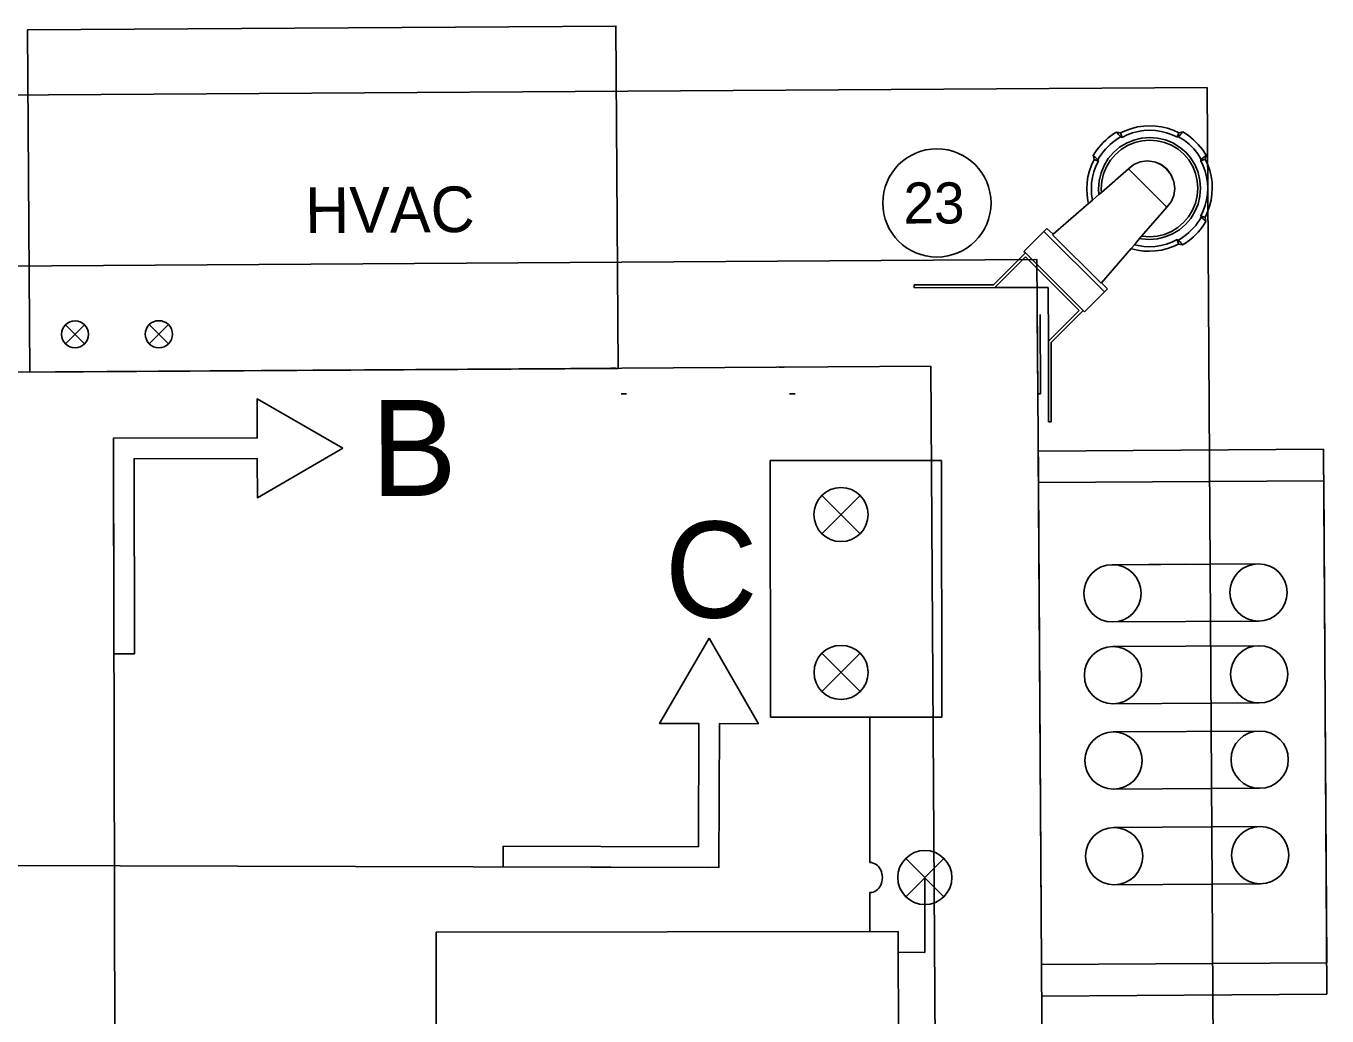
# Model space of a CAD drawing. Extents: x -2.6 to 16.3, y -2.7 to 7.5.
# Drawn here: x 12.505 to 16.306, y 4.389 to 7.281 of the extents above; entities that cross this region are included whole.
import ezdxf

# ---------------------------------------------------------------- set-up
doc = ezdxf.new("R2010")
doc.units = 0
for name, color, linetype in [('Default', 7, 'Continuous'), ('HS_Concrete_Object', 7, 'Continuous'), ('HS_Dimensions_and_Text', 7, 'Continuous'), ('HS_Electrical_Conduit', 7, 'Continuous'), ('HS_Electrical_Devices', 7, 'Continuous'), ('HS_Electrical_Enclosure', 7, 'Continuous'), ('HS_Existing', 7, 'Continuous'), ('PM_Pr_White', 7, 'Continuous'), ('SH_Matchline', 7, 'Continuous')]:
    doc.layers.add(name, color=color, linetype=linetype)

msp = doc.modelspace()

# ---------------------------------------------------------------- linework, layer by layer
at = {"layer": 'Default'}
for p, q in [((15.4598, 6.4421), (15.4613, 6.2066)), ((15.468, 6.4387), (15.4695, 6.2067)), ((15.4695, 6.2067), (15.4613, 6.2066))]:
    msp.add_line(p, q, dxfattribs=at)
at = {"layer": 'HS_Concrete_Object'}
for points in [[(14.235, 6.281), (14.2286, 7.281), (12.5099, 7.27), (12.5163, 6.27)], [(15.9556, 7.1018), (-0.0446, 6.9998), (0, 0), (16.0002, 0.1019)]]:
    msp.add_lwpolyline(points, close=True, dxfattribs=at)
for points in [[(15.4629, 5.9473), (15.4588, 6.5986), (0.4591, 6.5025), (0.4974, 0.5032), (0.9916, 0.5063)], [(0.7399, 0.7823), (0.7054, 6.1941), (15.1483, 6.2872)], [(15.1804, 1.2511), (15.1483, 6.2872)], [(15.4928, 1.2531), (15.462, 6.1014)]]:
    msp.add_lwpolyline(points, dxfattribs=at)
at = {"layer": 'HS_Dimensions_and_Text'}
for points in [[(13.4309, 6.0481), (13.1806, 6.1919), (13.1809, 6.0776), (12.7609, 6.0767), (12.7622, 5.4467), (12.8222, 5.4468), (12.821, 6.0168), (13.181, 6.0176), (13.1812, 5.9032)], [(14.5016, 5.4933), (14.6452, 5.2429), (14.5309, 5.2432), (14.5297, 4.8232), (13.8997, 4.825), (13.8998, 4.885), (14.4698, 4.8834), (14.4709, 5.2434), (14.3565, 5.2437)]]:
    msp.add_lwpolyline(points, close=True, dxfattribs=at)
for points in [[(12.7609, 6.0463), (12.7712, 1.2501)], [(5.2174, 4.8497), (14.4996, 4.8233)]]:
    msp.add_lwpolyline(points, dxfattribs=at)
at = {"layer": 'HS_Electrical_Conduit'}
for p, q in [((15.6787, 5.7075), (16.1056, 5.7102)), ((15.6798, 5.5402), (16.1067, 5.543)), ((15.6803, 5.4682), (16.1071, 5.4709)), ((15.6813, 5.301), (16.1082, 5.3037)), ((15.6818, 5.2189), (16.1087, 5.2217)), ((15.6829, 5.0517), (16.1098, 5.0544)), ((15.6836, 4.9398), (16.1105, 4.9425)), ((15.1312, 4.7937), (15.1314, 4.575)), ((15.6847, 4.7725), (16.1116, 4.7753)), ((15.1314, 4.575), (15.0536, 4.5752))]:
    msp.add_line(p, q, dxfattribs=at)
for centre in [(15.6793, 5.6239), (16.1061, 5.6266), (15.6808, 5.3846), (16.1077, 5.3873), (15.6824, 5.1353), (16.1093, 5.138), (16.111, 4.8589), (15.6841, 4.8562)]:
    msp.add_circle(centre, 0.0836, dxfattribs=at)
at = {"layer": 'HS_Electrical_Devices'}
for p, q in [((15.6748, 6.9602), (15.6671, 6.9542)), ((15.6828, 6.9658), (15.6748, 6.9602)), ((15.6911, 6.971), (15.6828, 6.9658)), ((15.6911, 6.971), (15.6936, 6.9682)), ((15.6911, 6.971), (15.7029, 6.9685)), ((15.6936, 6.9682), (15.6961, 6.9654)), ((15.7033, 6.957), (15.6951, 6.9521)), ((15.6961, 6.9654), (15.6985, 6.9626)), ((15.6985, 6.9626), (15.7009, 6.9598)), ((15.7009, 6.9598), (15.7033, 6.957)), ((15.719, 6.9759), (15.7029, 6.9685)), ((15.7072, 6.9557), (15.7029, 6.9685)), ((15.7072, 6.9557), (15.7033, 6.957)), ((15.7224, 6.963), (15.7072, 6.9557)), ((15.7357, 6.9818), (15.719, 6.9759)), ((15.7382, 6.9687), (15.7224, 6.963)), ((15.7528, 6.9861), (15.7357, 6.9818)), ((15.7545, 6.9729), (15.7382, 6.9687)), ((15.7703, 6.9887), (15.7528, 6.9861)), ((15.7711, 6.9754), (15.7545, 6.9729)), ((15.7879, 6.9555), (15.7645, 6.9536)), ((15.7879, 6.9896), (15.7703, 6.9887)), ((15.7879, 6.9763), (15.7711, 6.9754)), ((15.8056, 6.9889), (15.7879, 6.9896)), ((15.8047, 6.9756), (15.7879, 6.9763)), ((15.8112, 6.9537), (15.7879, 6.9555)), ((15.8213, 6.9731), (15.8047, 6.9756)), ((15.823, 6.9864), (15.8056, 6.9889)), ((15.8376, 6.9691), (15.8213, 6.9731)), ((15.8402, 6.9822), (15.823, 6.9864)), ((15.8534, 6.9634), (15.8376, 6.9691)), ((15.8569, 6.9764), (15.8402, 6.9822)), ((15.8534, 6.9634), (15.8693, 6.9565)), ((15.8729, 6.9691), (15.8569, 6.9764)), ((15.8693, 6.9565), (15.8696, 6.9595)), ((15.8724, 6.9576), (15.8693, 6.9565)), ((15.8729, 6.9691), (15.8696, 6.9595)), ((15.8724, 6.9576), (15.8748, 6.9604)), ((15.8885, 6.9475), (15.8724, 6.9576)), ((15.8729, 6.9691), (15.8847, 6.9717)), ((15.8748, 6.9604), (15.8773, 6.9633)), ((15.8773, 6.9633), (15.8797, 6.9661)), ((15.8797, 6.9661), (15.8822, 6.9689)), ((15.8822, 6.9689), (15.8847, 6.9717)), ((15.901, 6.9611), (15.8847, 6.9717)), ((15.9161, 6.9488), (15.901, 6.9611)), ((15.6335, 6.9189), (15.6279, 6.9109)), ((15.6395, 6.9266), (15.6335, 6.9189)), ((15.6459, 6.934), (15.6395, 6.9266)), ((15.6526, 6.9411), (15.6459, 6.934)), ((15.6597, 6.9479), (15.6526, 6.9411)), ((15.659, 6.9213), (15.6528, 6.914)), ((15.6655, 6.9282), (15.659, 6.9213)), ((15.6671, 6.9542), (15.6597, 6.9479)), ((15.6724, 6.9348), (15.6655, 6.9282)), ((15.6797, 6.941), (15.6724, 6.9348)), ((15.6873, 6.9467), (15.6797, 6.941)), ((15.7002, 6.9267), (15.6823, 6.9114)), ((15.6951, 6.9521), (15.6873, 6.9467)), ((15.7048, 6.9204), (15.6879, 6.9059)), ((15.7201, 6.939), (15.7002, 6.9267)), ((15.7237, 6.932), (15.7048, 6.9204)), ((15.7418, 6.948), (15.7201, 6.939)), ((15.7442, 6.9406), (15.7237, 6.932)), ((15.7645, 6.9536), (15.7418, 6.948)), ((15.7658, 6.9458), (15.7442, 6.9406)), ((15.7879, 6.9476), (15.7658, 6.9458)), ((15.81, 6.946), (15.7879, 6.9476)), ((15.8315, 6.9409), (15.81, 6.946)), ((15.834, 6.9484), (15.8112, 6.9537)), ((15.852, 6.9325), (15.8315, 6.9409)), ((15.8556, 6.9395), (15.834, 6.9484)), ((15.8709, 6.921), (15.852, 6.9325)), ((15.8755, 6.9273), (15.8556, 6.9395)), ((15.8877, 6.9066), (15.8709, 6.921)), ((15.8933, 6.9122), (15.8755, 6.9273)), ((15.9033, 6.9356), (15.8885, 6.9475)), ((15.9167, 6.9222), (15.9033, 6.9356)), ((15.9298, 6.9351), (15.9161, 6.9488)), ((15.9285, 6.9075), (15.9167, 6.9222)), ((15.9421, 6.92), (15.9298, 6.9351)), ((15.9528, 6.9038), (15.9421, 6.92)), ((15.6254, 6.8907), (15.6179, 6.8747)), ((15.6279, 6.9109), (15.6228, 6.9026)), ((15.6256, 6.9001), (15.6228, 6.9026)), ((15.6254, 6.8907), (15.6228, 6.9026)), ((15.6381, 6.8865), (15.6254, 6.8907)), ((15.6284, 6.8976), (15.6256, 6.9001)), ((15.6312, 6.8952), (15.6284, 6.8976)), ((15.6381, 6.8865), (15.6309, 6.8713)), ((15.634, 6.8928), (15.6312, 6.8952)), ((15.6369, 6.8904), (15.634, 6.8928)), ((15.6417, 6.8985), (15.6369, 6.8904)), ((15.6369, 6.8904), (15.6381, 6.8865)), ((15.6471, 6.9064), (15.6417, 6.8985)), ((15.6528, 6.914), (15.6471, 6.9064)), ((15.6671, 6.8936), (15.6548, 6.8736)), ((15.6735, 6.889), (15.6618, 6.87)), ((15.6823, 6.9114), (15.6671, 6.8936)), ((15.6879, 6.9059), (15.6735, 6.889)), ((15.7415, 6.8765), (15.76, 6.8847)), ((15.76, 6.8847), (15.7803, 6.8875)), ((15.7803, 6.8875), (15.801, 6.8846)), ((15.801, 6.8846), (15.8049, 6.883)), ((15.8049, 6.883), (15.8214, 6.8762)), ((15.8049, 6.883), (15.8205, 6.8764)), ((15.9021, 6.8898), (15.8877, 6.9066)), ((15.9084, 6.8945), (15.8933, 6.9122)), ((15.9136, 6.871), (15.9021, 6.8898)), ((15.9206, 6.8745), (15.9084, 6.8945)), ((15.9387, 6.8915), (15.9285, 6.9075)), ((15.9374, 6.8876), (15.9502, 6.8919)), ((15.9376, 6.8883), (15.9374, 6.8876)), ((15.9374, 6.8876), (15.9446, 6.8724)), ((15.9376, 6.8883), (15.9387, 6.8915)), ((15.9415, 6.8939), (15.9387, 6.8915)), ((15.9444, 6.8963), (15.9415, 6.8939)), ((15.9472, 6.8988), (15.9444, 6.8963)), ((15.95, 6.9012), (15.9472, 6.8988)), ((15.9528, 6.9038), (15.95, 6.9012)), ((15.9528, 6.9038), (15.9502, 6.8919)), ((15.9576, 6.8759), (15.9502, 6.8919)), ((15.612, 6.858), (15.6078, 6.8408)), ((15.6179, 6.8747), (15.612, 6.858)), ((15.6252, 6.8555), (15.621, 6.8391)), ((15.6309, 6.8713), (15.6252, 6.8555)), ((15.6459, 6.8519), (15.6403, 6.8291)), ((15.6548, 6.8736), (15.6459, 6.8519)), ((15.6471, 6.795), (15.7263, 6.8635)), ((15.6481, 6.8279), (15.6533, 6.8495)), ((15.6618, 6.87), (15.6533, 6.8495)), ((15.7263, 6.8635), (15.7415, 6.8765)), ((15.8378, 6.7522), (15.7263, 6.8635)), ((15.8205, 6.8764), (15.837, 6.8636)), ((15.8214, 6.8762), (15.8377, 6.8636)), ((15.837, 6.8636), (15.8374, 6.8633)), ((15.8374, 6.8633), (15.8505, 6.8464)), ((15.8377, 6.8636), (15.8503, 6.8473)), ((15.8503, 6.8473), (15.8571, 6.8309)), ((15.8505, 6.8464), (15.8571, 6.8309)), ((15.9221, 6.8505), (15.9136, 6.871)), ((15.9295, 6.853), (15.9206, 6.8745)), ((15.9272, 6.829), (15.9221, 6.8505)), ((15.935, 6.8302), (15.9295, 6.853)), ((15.9446, 6.8724), (15.9502, 6.8566)), ((15.9502, 6.8566), (15.9543, 6.8403)), ((15.9634, 6.8593), (15.9576, 6.8759)), ((15.9676, 6.8421), (15.9634, 6.8593)), ((15.9701, 6.8247), (15.9676, 6.8421)), ((15.6052, 6.8233), (15.6043, 6.8057)), ((15.6043, 6.8057), (15.6051, 6.788)), ((15.6078, 6.8408), (15.6052, 6.8233)), ((15.6066, 6.8344), (15.6052, 6.8233)), ((15.6078, 6.8408), (15.6066, 6.8344)), ((15.6185, 6.8225), (15.6176, 6.8057)), ((15.6176, 6.8057), (15.6184, 6.789)), ((15.6198, 6.8323), (15.6185, 6.8225)), ((15.621, 6.8391), (15.6198, 6.8323)), ((15.6403, 6.8291), (15.6385, 6.8058)), ((15.6385, 6.8058), (15.6398, 6.7887)), ((15.6481, 6.8279), (15.6463, 6.8058)), ((15.6463, 6.8058), (15.6471, 6.795)), ((15.8571, 6.8309), (15.8588, 6.8269)), ((15.8588, 6.8269), (15.8617, 6.8063)), ((15.8617, 6.8063), (15.8589, 6.786)), ((15.9271, 6.7848), (15.9289, 6.8069)), ((15.9289, 6.8069), (15.9272, 6.829)), ((15.9349, 6.7836), (15.9368, 6.8069)), ((15.9368, 6.8069), (15.935, 6.8302)), ((15.9543, 6.8403), (15.9568, 6.8237)), ((15.9576, 6.807), (15.9567, 6.7902)), ((15.9568, 6.8237), (15.9576, 6.807)), ((15.97, 6.7894), (15.9709, 6.807)), ((15.9709, 6.807), (15.9701, 6.8247)), ((15.6051, 6.788), (15.6077, 6.7706)), ((15.6077, 6.7706), (15.6096, 6.7625)), ((15.6096, 6.7625), (15.6209, 6.7724)), ((15.6184, 6.789), (15.6209, 6.7724)), ((15.6209, 6.7724), (15.6398, 6.7887)), ((15.6209, 6.7724), (15.6209, 6.7723)), ((15.6398, 6.7887), (15.6471, 6.795)), ((15.8508, 6.7675), (15.8378, 6.7522)), ((15.8589, 6.786), (15.8508, 6.7675)), ((15.9219, 6.7632), (15.9271, 6.7848)), ((15.9294, 6.7608), (15.9349, 6.7836)), ((15.9542, 6.7736), (15.95, 6.7572)), ((15.9567, 6.7902), (15.9542, 6.7736)), ((15.9632, 6.7547), (15.9674, 6.7719)), ((15.9674, 6.7719), (15.97, 6.7894)), ((15.5056, 6.6725), (15.6096, 6.7625)), ((15.8378, 6.7522), (15.7645, 6.6669)), ((15.9018, 6.7237), (15.9134, 6.7427)), ((15.9081, 6.7191), (15.9204, 6.7391)), ((15.9134, 6.7427), (15.9219, 6.7632)), ((15.9204, 6.7391), (15.9294, 6.7608)), ((15.9443, 6.7414), (15.9371, 6.7262)), ((15.95, 6.7572), (15.9443, 6.7414)), ((15.9499, 6.722), (15.9573, 6.738)), ((15.9573, 6.738), (15.9632, 6.7547)), ((15.488, 6.69), (15.4788, 6.6807)), ((15.5056, 6.6725), (15.488, 6.69)), ((15.8515, 6.6807), (15.8705, 6.6923)), ((15.8705, 6.6923), (15.8873, 6.7068)), ((15.8751, 6.686), (15.8929, 6.7013)), ((15.8873, 6.7068), (15.9018, 6.7237)), ((15.8929, 6.7013), (15.9081, 6.7191)), ((15.9097, 6.6845), (15.9163, 6.6914)), ((15.9163, 6.6914), (15.9224, 6.6987)), ((15.9224, 6.6987), (15.9282, 6.7063)), ((15.9282, 6.7063), (15.9335, 6.7142)), ((15.9335, 6.7142), (15.9384, 6.7223)), ((15.9357, 6.6861), (15.9417, 6.6938)), ((15.9371, 6.7262), (15.9499, 6.722)), ((15.9384, 6.7223), (15.9371, 6.7262)), ((15.9384, 6.7223), (15.9412, 6.7199)), ((15.9412, 6.7199), (15.9441, 6.7175)), ((15.9417, 6.6938), (15.9473, 6.7018)), ((15.9441, 6.7175), (15.9469, 6.7151)), ((15.9469, 6.7151), (15.9497, 6.7126)), ((15.9473, 6.7018), (15.9524, 6.7101)), ((15.9497, 6.7126), (15.9524, 6.7101)), ((15.9499, 6.722), (15.9524, 6.7101)), ((15.4208, 6.6226), (15.4788, 6.6807)), ((15.4788, 6.6807), (15.6557, 6.5041)), ((15.5041, 6.6712), (15.5056, 6.6725)), ((15.5041, 6.6712), (15.6462, 6.5294)), ((15.7587, 6.6602), (15.7432, 6.6422)), ((15.7645, 6.6669), (15.7587, 6.6602)), ((15.7587, 6.6602), (15.764, 6.659)), ((15.764, 6.659), (15.7873, 6.6572)), ((15.7645, 6.6669), (15.7653, 6.6667)), ((15.7653, 6.6667), (15.7874, 6.6651)), ((15.7873, 6.6572), (15.8107, 6.6591)), ((15.7874, 6.6651), (15.8095, 6.6669)), ((15.8095, 6.6669), (15.831, 6.6721)), ((15.8107, 6.6591), (15.8334, 6.6647)), ((15.831, 6.6721), (15.8515, 6.6807)), ((15.8334, 6.6647), (15.8551, 6.6737)), ((15.868, 6.657), (15.8528, 6.6497)), ((15.8551, 6.6737), (15.8751, 6.686)), ((15.868, 6.657), (15.8723, 6.6442)), ((15.868, 6.657), (15.8719, 6.6557)), ((15.8719, 6.6557), (15.8801, 6.6606)), ((15.8743, 6.6529), (15.8719, 6.6557)), ((15.8767, 6.6501), (15.8743, 6.6529)), ((15.8801, 6.6606), (15.888, 6.666)), ((15.888, 6.666), (15.8956, 6.6717)), ((15.8924, 6.6469), (15.9004, 6.6525)), ((15.8956, 6.6717), (15.9028, 6.6779)), ((15.9004, 6.6525), (15.9082, 6.6584)), ((15.9028, 6.6779), (15.9097, 6.6845)), ((15.9082, 6.6584), (15.9156, 6.6648)), ((15.9156, 6.6648), (15.9226, 6.6716)), ((15.9226, 6.6716), (15.9294, 6.6787)), ((15.9294, 6.6787), (15.9357, 6.6861)), ((15.3319, 6.5249), (15.4251, 6.6183)), ((15.4251, 6.6183), (15.4208, 6.6226)), ((15.5934, 6.4503), (15.4251, 6.6183)), ((15.7336, 6.631), (15.6474, 6.5309)), ((15.7432, 6.6422), (15.7336, 6.631)), ((15.7336, 6.631), (15.735, 6.6305)), ((15.735, 6.6305), (15.7522, 6.6263)), ((15.7539, 6.6396), (15.7432, 6.6422)), ((15.7522, 6.6263), (15.7696, 6.6238)), ((15.7705, 6.6371), (15.7539, 6.6396)), ((15.7696, 6.6238), (15.7873, 6.623)), ((15.7873, 6.6364), (15.7705, 6.6371)), ((15.8041, 6.6373), (15.7873, 6.6364)), ((15.7873, 6.623), (15.8049, 6.624)), ((15.8207, 6.6398), (15.8041, 6.6373)), ((15.8049, 6.624), (15.8224, 6.6266)), ((15.837, 6.644), (15.8207, 6.6398)), ((15.8224, 6.6266), (15.8396, 6.6309)), ((15.8528, 6.6497), (15.837, 6.644)), ((15.8396, 6.6309), (15.8562, 6.6368)), ((15.8562, 6.6368), (15.8723, 6.6442)), ((15.8841, 6.6417), (15.8723, 6.6442)), ((15.8792, 6.6473), (15.8767, 6.6501)), ((15.8816, 6.6445), (15.8792, 6.6473)), ((15.8841, 6.6417), (15.8816, 6.6445)), ((15.8841, 6.6417), (15.8924, 6.6469)), ((15.4251, 6.6067), (15.3353, 6.5167)), ((15.5818, 6.4503), (15.4251, 6.6067)), ((15.0998, 6.5247), (15.3319, 6.5249)), ((15.0998, 6.5165), (15.0998, 6.5247)), ((15.0998, 6.5165), (15.3353, 6.5167)), ((15.3353, 6.5167), (15.4919, 6.5169)), ((15.4919, 6.5169), (15.492, 6.3603)), ((15.6557, 6.5041), (15.5977, 6.446)), ((15.6474, 6.5309), (15.6462, 6.5294)), ((15.665, 6.5134), (15.6474, 6.5309)), ((15.665, 6.5134), (15.6557, 6.5041)), ((15.492, 6.3603), (15.5818, 6.4503)), ((15.5934, 6.4503), (15.5002, 6.3569)), ((15.5977, 6.446), (15.5934, 6.4503)), ((12.6765, 6.3525), (12.6205, 6.4085)), ((12.6205, 6.3525), (12.6764, 6.4085)), ((12.9215, 6.3528), (12.8656, 6.4087)), ((12.8656, 6.3527), (12.9215, 6.4087)), ((15.492, 6.3603), (15.4922, 6.1248)), ((15.5002, 6.3569), (15.5004, 6.1248)), ((14.2441, 6.2062), (14.26, 6.2062)), ((14.7362, 6.2066), (14.7521, 6.2066)), ((15.5004, 6.1248), (15.4922, 6.1248)), ((15.1798, 6.0122), (14.6798, 6.0117)), ((14.6805, 5.2617), (14.6798, 6.0117)), ((15.1805, 5.2622), (15.1798, 6.0122)), ((14.942, 5.798), (14.8301, 5.9099)), ((14.8302, 5.798), (14.942, 5.9099)), ((14.9425, 5.3369), (14.8306, 5.4487)), ((14.8306, 5.3368), (14.9424, 5.4487)), ((15.1805, 5.2622), (14.6805, 5.2617)), ((14.9702, 5.262), (14.9706, 4.8376)), ((15.1871, 4.7377), (15.0752, 4.8496)), ((15.0752, 4.7377), (15.1871, 4.8496)), ((14.9708, 4.6356), (14.9707, 4.7495)), ((15.0535, 4.6356), (13.7035, 4.6344)), ((13.7035, 4.6344), (13.7057, 2.2844)), ((15.0535, 4.6356), (15.0557, 2.2856))]:
    msp.add_line(p, q, dxfattribs=at)
for centre, radius in [((15.1664, 6.7642), 0.1581), ((12.6485, 6.3805), 0.0396), ((12.8935, 6.3807), 0.0396), ((14.8861, 5.854), 0.0791), ((14.8865, 5.3928), 0.0791), ((15.1312, 4.7937), 0.0791)]:
    msp.add_circle(centre, radius, dxfattribs=at)
msp.add_ellipse((14.9707, 4.7935), major_axis=(0, -0.044), ratio=0.825637, start_param=0, end_param=3.141593, dxfattribs=at)
at = {"layer": 'HS_Electrical_Enclosure'}
for p, q in [((15.4629, 5.9473), (16.2964, 5.9526)), ((16.2964, 5.9526), (16.306, 4.4526)), ((15.4725, 4.4473), (16.306, 4.4526))]:
    msp.add_line(p, q, dxfattribs=at)
at = {"layer": 'HS_Existing'}
for p, q in [((15.4624, 6.0394), (16.2958, 6.0447)), ((16.3054, 4.5448), (16.2958, 6.0447)), ((15.4719, 4.5395), (15.4624, 6.0394)), ((15.4719, 4.5395), (16.3054, 4.5448))]:
    msp.add_line(p, q, dxfattribs=at)
at = {"layer": 'PM_Pr_White'}
for p, q in [((14.2128, 6.2812), (14.2286, 6.2813)), ((14.7048, 6.2843), (14.7207, 6.2844))]:
    msp.add_line(p, q, dxfattribs=at)
at = {"layer": 'SH_Matchline'}
for p, q in [((15.6787, 5.7075), (16.1056, 5.7102)), ((15.6787, 5.7075), (15.8927, 5.7089)), ((15.6798, 5.5402), (16.1067, 5.543)), ((15.6803, 5.4682), (16.1071, 5.4709)), ((15.6813, 5.301), (16.1082, 5.3037)), ((15.6818, 5.2189), (16.1087, 5.2217)), ((15.6829, 5.0517), (16.1098, 5.0544)), ((15.6836, 4.9398), (16.1105, 4.9425)), ((15.6847, 4.7725), (16.1116, 4.7753))]:
    msp.add_line(p, q, dxfattribs=at)

# ---------------------------------------------------------------- texts
at = {"layer": 'HS_Dimensions_and_Text'}
for s, height, rotation, p in [('HVAC', 0.13333, 0.365, (13.3212, 6.6761)), ('B', 0.2808, 0.1231, (13.5134, 5.9079)), ('C', 0.2808, 359.8371, (14.371, 5.5532))]:
    msp.add_text(s, height=height, rotation=rotation, dxfattribs=at).set_placement(p)
at = {"layer": 'HS_Electrical_Devices'}
msp.add_text('23', height=0.12, rotation=0.0523, dxfattribs=at).set_placement((15.0687, 6.7041))

doc.saveas('drawing.dxf')
